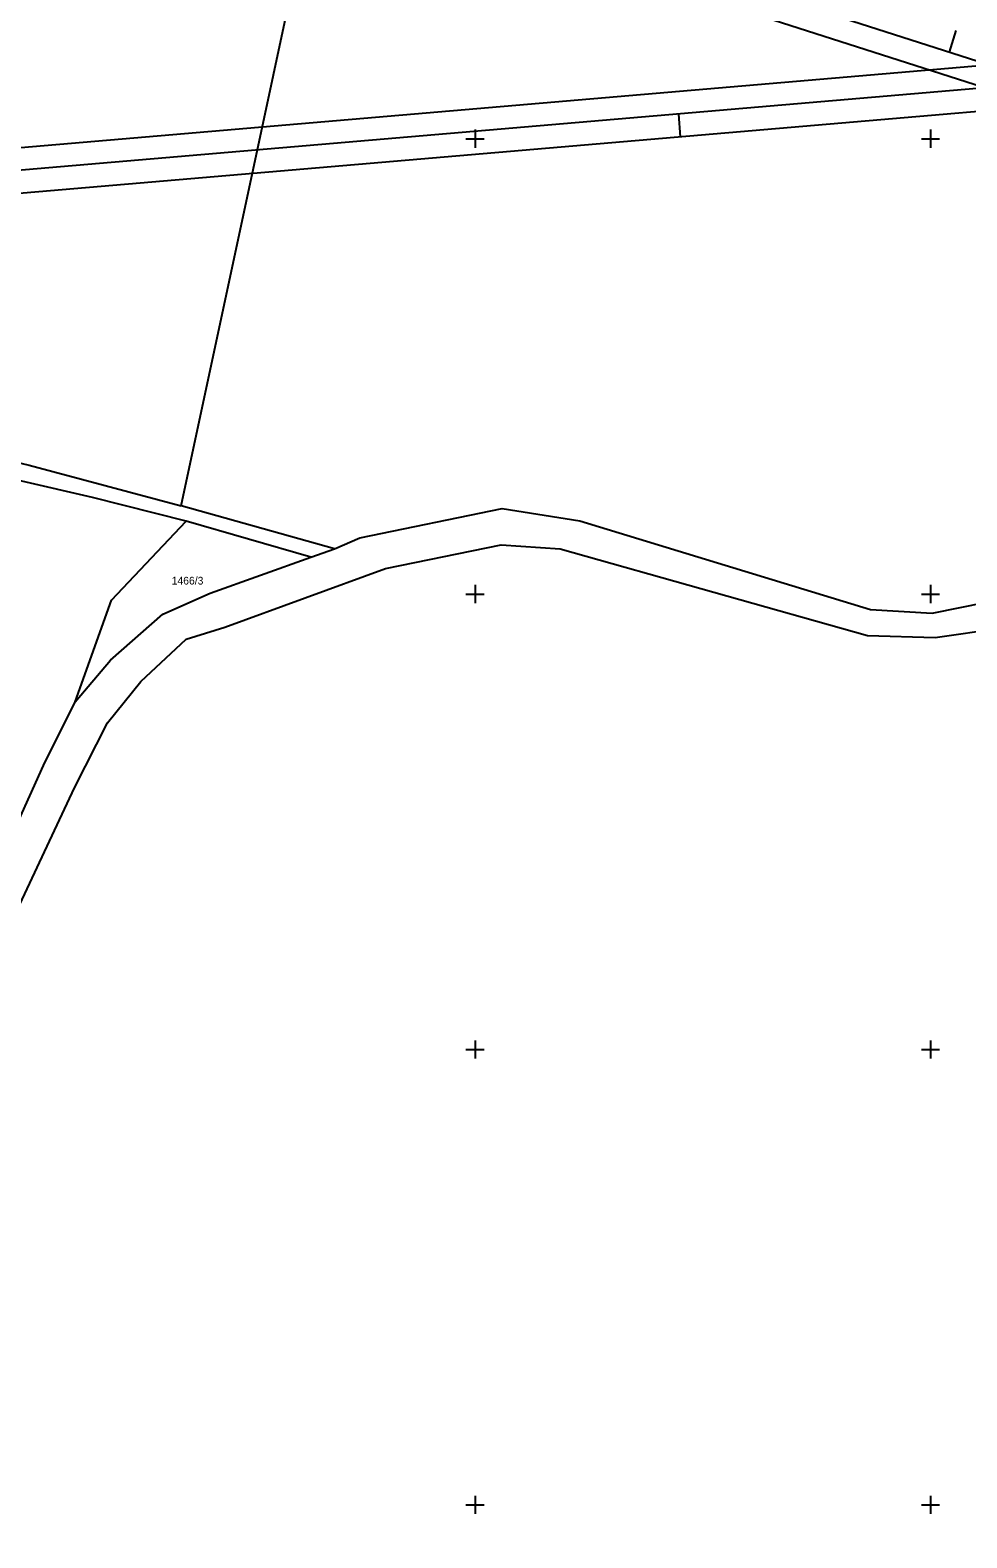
# Model space of a CAD drawing. Extents: x -779302 to -774398, y -1144902 to -1142831.
# Drawn here: x -777897.7 to -777692, y -1144107.2 to -1143776.2 of the extents above; entities that cross this region are included whole.
import ezdxf

# ---------------------------------------------------------------- set-up
doc = ezdxf.new("R2010")
doc.units = 0
for name, color, linetype in [('hektosit - Vrstva 5', 7, 'Continuous'), ('Hranice parcel', 7, 'Continuous'), ('Parcelní čísla', 7, 'Continuous'), ('Vrstva 1', 7, 'Continuous')]:
    doc.layers.add(name, color=color, linetype=linetype)

msp = doc.modelspace()

# ---------------------------------------------------------------- linework, layer by layer
at = {"layer": 'hektosit - Vrstva 5'}
for p, q in [((-777802, -1143800), (-777798, -1143800)), ((-777800, -1143798), (-777800, -1143802)), ((-777702, -1143800), (-777698, -1143800)), ((-777700, -1143798), (-777700, -1143802)), ((-777802, -1143900), (-777798, -1143900)), ((-777800, -1143898), (-777800, -1143902)), ((-777702, -1143900), (-777698, -1143900)), ((-777700, -1143898), (-777700, -1143902)), ((-777800, -1143998), (-777800, -1144002)), ((-777700, -1143998), (-777700, -1144002)), ((-777802, -1144000), (-777798, -1144000)), ((-777702, -1144000), (-777698, -1144000)), ((-777800, -1144098), (-777800, -1144102)), ((-777700, -1144098), (-777700, -1144102)), ((-777802, -1144100), (-777798, -1144100)), ((-777702, -1144100), (-777698, -1144100))]:
    msp.add_line(p, q, dxfattribs=at)
at = {"layer": 'Hranice parcel'}
for p, q in [((-777830.91, -1143890.09), (-777864.55, -1143880.59)), ((-777836.08, -1143891.9), (-777863.49, -1143883.95)), ((-777836.08, -1143891.9), (-777830.91, -1143890.09))]:
    msp.add_line(p, q, dxfattribs=at)
for points in [[(-777864.55, -1143880.59), (-777823.97, -1143691.22), (-777815.03, -1143678.47)], [(-778064.15, -1143832.38), (-777897.94, -1143871.72), (-777864.55, -1143880.59)], [(-777863.49, -1143883.95), (-777884, -1143878.82), (-778060.8, -1143837.94)], [(-777830.91, -1143890.09), (-777825.32, -1143887.66), (-777794.09, -1143881.19), (-777777.01, -1143883.9), (-777713.2, -1143903.35), (-777699.62, -1143904.18), (-777675.76, -1143899.35), (-777628.63, -1143877.96)], [(-777887.81, -1143923.63), (-777879.86, -1143901.34), (-777863.49, -1143883.95)], [(-778009.9, -1144107.25), (-777953.32, -1144054.13), (-777934.54, -1144033.2), (-777924.66, -1144019.03), (-777912.62, -1143995.04), (-777887.98, -1143942.51), (-777880.73, -1143928.25), (-777873.39, -1143919.21), (-777863.44, -1143909.89), (-777854.97, -1143907.29), (-777819.69, -1143894.41), (-777794.31, -1143889.17), (-777781.32, -1143890.06), (-777713.84, -1143909.1), (-777698.95, -1143909.5), (-777684.66, -1143907.5), (-777671.93, -1143904.47), (-777632.79, -1143892.89), (-777622.97, -1143889.62)], [(-777887.81, -1143923.63), (-777880.06, -1143914.49), (-777868.59, -1143904.42), (-777858.15, -1143899.78), (-777836.08, -1143891.9)], [(-778008.42, -1144097.2), (-777957.39, -1144049.44), (-777938.98, -1144029.6), (-777930.61, -1144016.95), (-777894.78, -1143937.67), (-777887.81, -1143923.63)]]:
    msp.add_lwpolyline(points, dxfattribs=at)
at = {"layer": 'Vrstva 1'}
for p, q in [((-777694.39, -1143776.21), (-777695.91, -1143780.97)), ((-777755.36, -1143794.59), (-777754.94, -1143799.56))]:
    msp.add_line(p, q, dxfattribs=at)
for points in [[(-776606.88, -1143822.95), (-777806.9, -1143438.86), (-777897.43, -1143721.71), (-776697.42, -1144105.81)], [(-776700.65, -1144099.52), (-777891.15, -1143718.47), (-777803.66, -1143445.14), (-776613.17, -1143826.19)], [(-777571, -1143485.76), (-778617.18, -1143575.21), (-778591.88, -1143871.12), (-777545.7, -1143781.67)], [(-777551.11, -1143777.12), (-778587.32, -1143865.71), (-778611.77, -1143579.77), (-777575.56, -1143491.17)], [(-777580.11, -1143496.57), (-778407.09, -1143567.28), (-778383.5, -1143843.27), (-777556.51, -1143772.57)]]:
    msp.add_lwpolyline(points, close=True, dxfattribs=at)

# ---------------------------------------------------------------- texts
at = {"layer": 'Parcelní čísla'}
msp.add_text('1466/3', height=1.7, dxfattribs=at).set_placement((-777866.63, -1143897.9))

doc.saveas('drawing.dxf')
